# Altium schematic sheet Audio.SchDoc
size A4; Revision: B.2
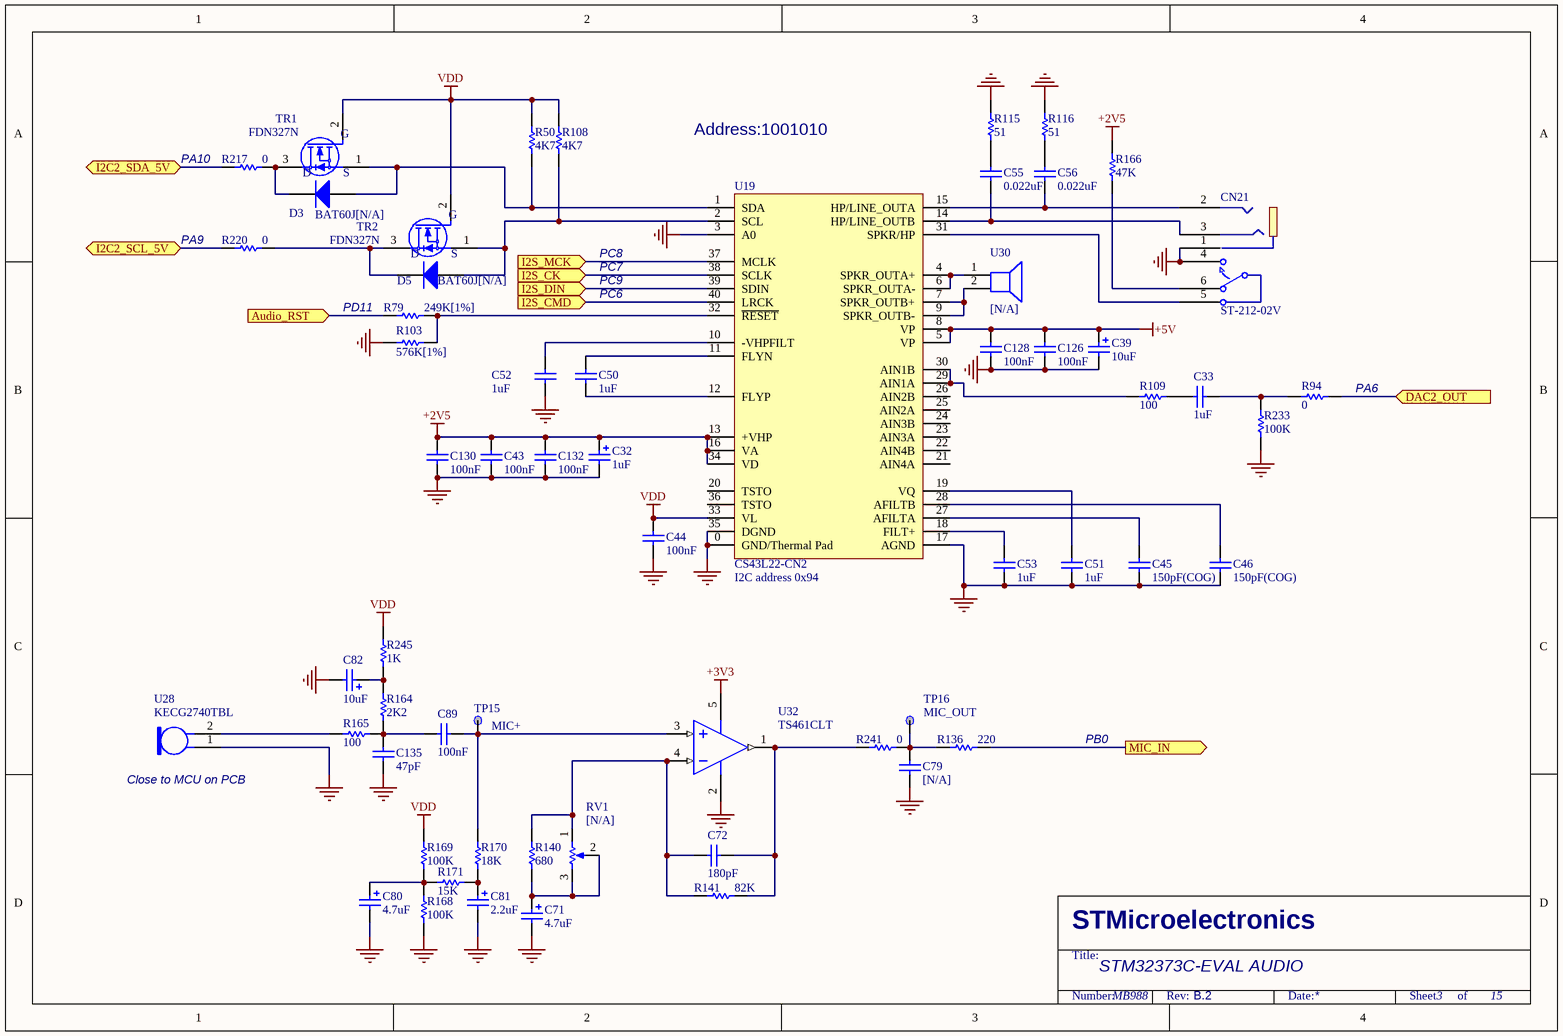
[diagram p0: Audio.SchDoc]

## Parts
C32  1uF  [TAN-A]
C33  1uF  [0603C]
C39  10uF  [TAN-A]
C43  100nF  [0603C]
C44  100nF  [0603C]
C45  150pF(COG)  [0603C]
C46  150pF(COG)  [0603C]
C50  1uF  [0603C]
C51  1uF  [0603C]
C52  1uF  [0603C]
C53  1uF  [0603C]
C55  0.022uF  [0603C]
C56  0.022uF  [0603C]
C71  4.7uF  [TAN-A]
C72  180pF  [0603C]
C79  [N/A]  [0603C]
C80  4.7uF  [TAN-A]
C81  2.2uF  [0805C]
C82  10uF  [TAN-A]
C89  100nF  [0603C]
C126  100nF  [0603C]
C128  100nF  [0603C]
C130  100nF  [0603C]
C132  100nF  [0603C]
C135  47pF  [0603C]
CN21  ST-212-02V  [ST-212-02V]
D3  BAT60J[N/A]  [SOD-323]
D5  BAT60J[N/A]  [SOD-323]
R50  4K7  [0603R]
R79  249K[1%]  [0603R]
R94  0  [0603R]
R103  576K[1%]  [0603R]
R108  4K7  [0603R]
R109  100  [0603R]
R115  51  [0603R]
R116  51  [0603R]
R136  220  [0603R]
R140  680  [0603R]
R141  82K  [0603R]
R164  2K2  [0603R]
R165  100  [0603R]
R166  47K  [0603R]
R168  100K  [0603R]
R169  100K  [0603R]
R170  18K  [0603R]
R171  15K  [0603R]
R217  0  [0603R]
R220  0  [0603R]
R233  100K  [0603R]
R241  0  [0603R]
R245  1K  [0603R]
RV1  [N/A]  [3314-J]
TP15  MIC+  [TP]
TP16  MIC_OUT  [TP]
TR1  FDN327N  [SOT-23]
TR2  FDN327N  [SOT-23]
U19  CS43L22-CN2  [QFN40(6*6)]
U28  KECG2740TBL  [KEC2740]
U30  [N/A]  [KS1708]
U32  TS461CLT  [SOT-23-5L]

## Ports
Audio_RST (in), DAC2_OUT (in), I2C2_SCL_5V (bidir), I2C2_SDA_5V (bidir), I2S_CK (in), I2S_CMD (in), I2S_DIN (in), I2S_MCK (in), MIC_IN (out)

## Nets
+2V5: C32.1 C43.1 C130.1 C132.1 R166.1 U19.13(+VHP) U19.16(VA) U19.34(VD)
+3V3: U32.5(VCC)
+5V: C39.1 C126.1 C128.1 U19.5(VP) U19.8(VP)
GND: C32.2 C39.2 C43.2 C44.2 C45.1 C46.1 C51.1 C52.2 C53.1 C71.2 C79.2 C80.2 C81.2 C82.2 C126.2 C128.2 C130.2 C132.2 C135.2 CN21.1 CN21.4 R103.1 R115.1 R116.1 R168.2 R233.2 U19.0(GND/Thermal_Pad) U19.3(A0) U19.17(AGND) U19.35(DGND) U28.1 U32.2(VDD)
VDD: C44.1 R50.2 R108.2 R169.1 R245.2 TR1.2(G) TR2.2(G) U19.33(VL)
Audio_RST: R79.2 ; port Audio_RST
DAC2_OUT: R94.2 ; port DAC2_OUT
I2C2_SCL_5V: R220.1 ; port I2C2_SCL_5V
I2C2_SDA_5V: R217.1 ; port I2C2_SDA_5V
I2S_CK: U19.38(SCLK) ; port I2S_CK
I2S_CMD: U19.40(LRCK) ; port I2S_CMD
I2S_DIN: U19.39(SDIN) ; port I2S_DIN
I2S_MCK: U19.37(MCLK) ; port I2S_MCK
MIC_IN: R136.1 ; port MIC_IN
NetC33_1: C33.1 R109.1
NetC33_2: C33.2 R94.1 R233.1
NetC45_2: C45.2 U19.27(AFILTA)
NetC46_2: C46.2 U19.28(AFILTB)
NetC50_1: C50.1 U19.12(FLYP)
NetC50_2: C50.2 U19.11(FLYN)
NetC51_2: C51.2 U19.19(VQ)
NetC52_1: C52.1 U19.10(-VHPFILT)
NetC53_2: C53.2 U19.18(FILT+)
NetC55_1: C55.1 R115.2
NetC55_2: C55.2 CN21.3 U19.14(HP/LINE_OUTB)
NetC56_1: C56.1 R116.2
NetC56_2: C56.2 CN21.2 U19.15(HP/LINE_OUTA)
NetC71_1: C71.1 R140.2 RV1.2(TAP) RV1.3(TOP)
NetC72_1: C72.1 R140.1 R141.2 RV1.1(BOT) U32.4(IN-)
NetC72_2: C72.2 R141.1 R241.2 U32.1(OUT)
NetC79_1: C79.1 R136.2 R241.1 TP16.1
NetC80_1: C80.1 R168.1 R169.2 R171.1
NetC81_1: C81.1 R170.1 R171.2
NetC82_1: C82.1 R164.2 R245.1
NetC89_1: C89.1 C135.1 R164.1 R165.1
NetC89_2: C89.2 R170.2 TP15.1 U32.3(IN+)
NetCN21_5: CN21.5 U19.31(SPKR/HP)
NetCN21_6: CN21.6 R166.2
NetD3_1: D3.1(A) R50.1 TR1.1(S) U19.1(SDA)
NetD3_2: D3.2(K) R217.2 TR1.3(D)
NetD5_1: D5.1(A) R108.1 TR2.1(S) U19.2(SCL)
NetD5_2: D5.2(K) R220.2 TR2.3(D)
NetR79_1: R79.1 R103.2 U19.32(~{RESET})
NetR109_2: R109.2 U19.29(AIN1A) U19.30(AIN1B)
NetR165_2: R165.2 U28.2
NetU19_4: U19.4(SPKR_OUTA+) U19.6(SPKR_OUTA-) U30.1(+)
NetU19_7: U19.7(SPKR_OUTB+) U19.9(SPKR_OUTB-) U30.2(-)

Not connected (* = marked no-connect by the designer): U19 20(TSTO) 21(AIN4A) 22(AIN4B) 23(AIN3A) 24(AIN3B) 25(AIN2A) 26(AIN2B) 36(TSTO)

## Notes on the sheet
- (near R217) PA10
- Address:1001010
- (near R220) PA9
- PD11
- PC8
- PC9
- PC6
- PC7
- (near R94) PA6
- (near U19) I2C address 0x94
- (near U28) Close to MCU on PCB
- PB0
- STM32373C-EVAL AUDIO
- MB988
- 3
- 15

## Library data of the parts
C32 = Cap Pol1: Polarized Capacitor (Radial); Value: 47uF
C33 C45 C46 C50-C53 C55 C56 C79 = CAP: Capacitor; Value: 100nF
C39 = Cap Pol1: Polarized Capacitor (Radial)
C43 C44 C126 C128 C130 C132 = Cap: Capacitor; Value: 10nF
C71 C80-C82 = Cap Pol1: Polarized Capacitor (Radial); Value: 100pF
C72 C89 C135 = CAP: Capacitor; Value: 100pF
D3 D5 = Diode: Default Diode; Code - JEDEC: DO-214-AB
R50 R108 R136 R140 R141 R164 R165 R168-R171 R217 R220 R241 = Res1: Resistor; Value: 1K
R79 R94 R103 R109 R115 R116 R166 R233 = res1: Resistor; Value: 1K
R245 = Res1: Resistor
RV1 = RV
TP15 TP16 = TP
TR1 TR2 = 2N7000
U19 = CS43L22
U28 = Mic2: Microphone
U30 = Speaker: Loudspeaker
